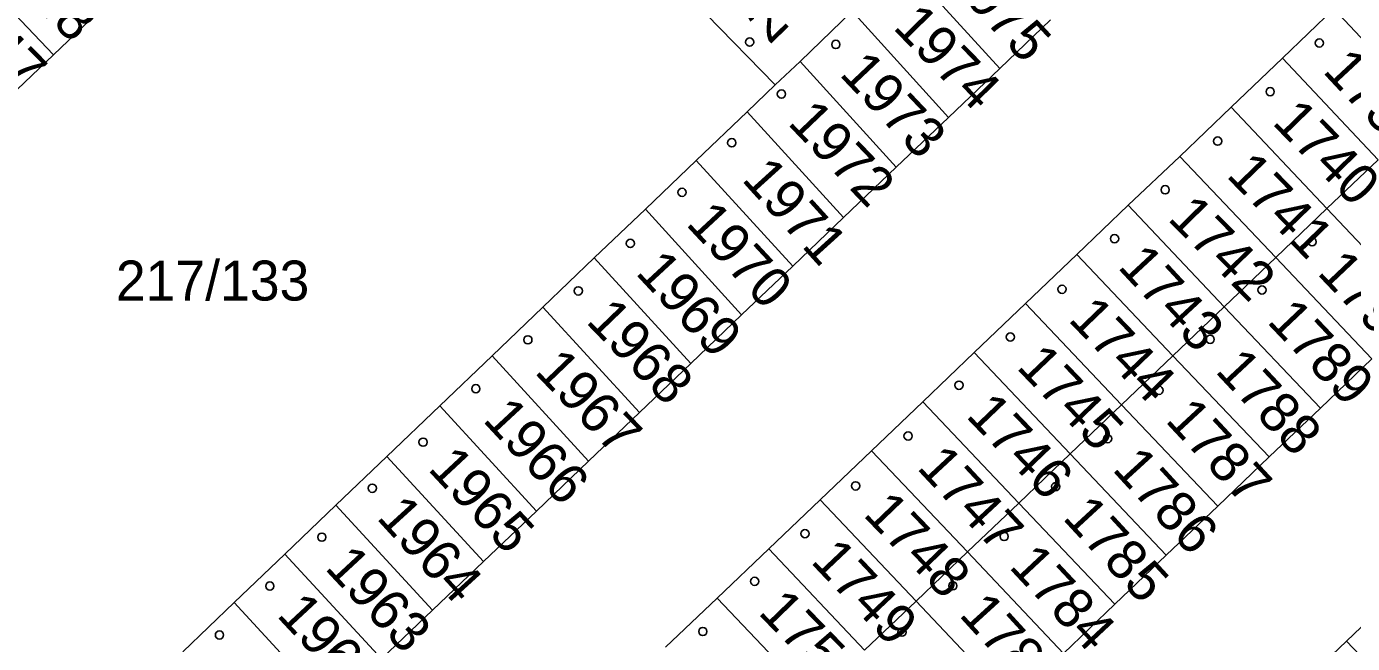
# Model space of a CAD drawing. Extents: x -735249 to -729401, y -1124843 to -1121828.
# Drawn here: x -733413.7 to -733357.4, y -1123214.1 to -1123187.9 of the extents above; entities that cross this region are included whole.
import ezdxf

# ---------------------------------------------------------------- set-up
doc = ezdxf.new("R2010")
doc.units = 0
for name, color, linetype in [('Vrstva 1', 7, 'Continuous'), ('Vrstva 18', 7, 'Continuous'), ('Vrstva 19', 7, 'Continuous'), ('Vrstva 25', 7, 'Continuous')]:
    doc.layers.add(name, color=color, linetype=linetype)

msp = doc.modelspace()

# ---------------------------------------------------------------- linework, layer by layer
at = {"layer": 'Vrstva 1'}
for points in [[(-733416.69, -1123184.71), (-733412.54, -1123189.07)], [(-733376.45, -1123185.14), (-733372.35, -1123189.66)], [(-733410.37, -1123187), (-733412.54, -1123189.07)], [(-733384.81, -1123187.34), (-733381.88, -1123190.35)], [(-733380.83, -1123189.35), (-733378.61, -1123187.22)], [(-733378.61, -1123187.22), (-733374.52, -1123191.73)], [(-733372.35, -1123189.66), (-733370.19, -1123187.59)], [(-733358.16, -1123187.12), (-733360.34, -1123189.21)], [(-733358.16, -1123187.12), (-733354.09, -1123191.44)], [(-733412.54, -1123189.07), (-733414.69, -1123191.13)], [(-733360.34, -1123189.21), (-733362.52, -1123191.3)], [(-733360.34, -1123189.21), (-733356.27, -1123193.53)], [(-733381.88, -1123190.35), (-733380.83, -1123189.35)], [(-733380.83, -1123189.35), (-733376.74, -1123193.85)], [(-733374.52, -1123191.73), (-733372.35, -1123189.66)], [(-733383.07, -1123191.49), (-733381.88, -1123190.35)], [(-733385.24, -1123193.57), (-733383.07, -1123191.49)], [(-733383.07, -1123191.49), (-733378.98, -1123195.99)], [(-733362.52, -1123191.3), (-733364.7, -1123193.39)], [(-733362.52, -1123191.3), (-733358.45, -1123195.61)], [(-733376.74, -1123193.85), (-733374.52, -1123191.73)], [(-733387.4, -1123195.64), (-733385.24, -1123193.57)], [(-733385.24, -1123193.57), (-733381.14, -1123198.06)], [(-733364.7, -1123193.39), (-733366.89, -1123195.47)], [(-733364.7, -1123193.39), (-733360.62, -1123197.69)], [(-733358.45, -1123195.61), (-733356.27, -1123193.53)], [(-733378.98, -1123195.99), (-733376.74, -1123193.85)], [(-733366.89, -1123195.47), (-733369.07, -1123197.56)], [(-733366.89, -1123195.47), (-733362.81, -1123199.78)], [(-733389.57, -1123197.71), (-733387.4, -1123195.64)], [(-733387.4, -1123195.64), (-733383.31, -1123200.13)], [(-733381.14, -1123198.06), (-733378.98, -1123195.99)], [(-733360.62, -1123197.69), (-733358.45, -1123195.61)], [(-733358.45, -1123195.61), (-733354.37, -1123199.92)], [(-733391.75, -1123199.8), (-733389.57, -1123197.71)], [(-733389.57, -1123197.71), (-733385.47, -1123202.2)], [(-733369.07, -1123197.56), (-733371.25, -1123199.65)], [(-733369.07, -1123197.56), (-733364.99, -1123201.87)], [(-733362.81, -1123199.78), (-733360.62, -1123197.69)], [(-733360.62, -1123197.69), (-733356.54, -1123202)], [(-733383.31, -1123200.13), (-733381.14, -1123198.06)], [(-733393.91, -1123201.87), (-733391.75, -1123199.8)], [(-733391.75, -1123199.8), (-733387.65, -1123204.28)], [(-733371.25, -1123199.65), (-733373.43, -1123201.73)], [(-733371.25, -1123199.65), (-733367.17, -1123203.95)], [(-733364.99, -1123201.87), (-733362.81, -1123199.78)], [(-733362.81, -1123199.78), (-733358.73, -1123204.09)], [(-733385.47, -1123202.2), (-733383.31, -1123200.13)], [(-733396.13, -1123204), (-733393.91, -1123201.87)], [(-733393.91, -1123201.87), (-733389.81, -1123206.35)], [(-733387.65, -1123204.28), (-733385.47, -1123202.2)], [(-733373.43, -1123201.73), (-733375.62, -1123203.82)], [(-733373.43, -1123201.73), (-733369.35, -1123206.04)], [(-733367.17, -1123203.95), (-733364.99, -1123201.87)], [(-733364.99, -1123201.87), (-733360.91, -1123206.17)], [(-733358.73, -1123204.09), (-733356.54, -1123202)], [(-733375.62, -1123203.82), (-733377.8, -1123205.91)], [(-733375.62, -1123203.82), (-733371.54, -1123208.13)], [(-733369.35, -1123206.04), (-733367.17, -1123203.95)], [(-733367.17, -1123203.95), (-733363.09, -1123208.26)], [(-733398.38, -1123206.15), (-733396.13, -1123204)], [(-733396.13, -1123204), (-733392.03, -1123208.47)], [(-733389.81, -1123206.35), (-733387.65, -1123204.28)], [(-733360.91, -1123206.17), (-733358.73, -1123204.09)], [(-733400.54, -1123208.22), (-733398.38, -1123206.15)], [(-733398.38, -1123206.15), (-733394.28, -1123210.62)], [(-733377.8, -1123205.91), (-733379.98, -1123208)], [(-733377.8, -1123205.91), (-733373.72, -1123210.21)], [(-733371.54, -1123208.13), (-733369.35, -1123206.04)], [(-733369.35, -1123206.04), (-733365.28, -1123210.35)], [(-733363.09, -1123208.26), (-733360.91, -1123206.17)], [(-733392.03, -1123208.47), (-733389.81, -1123206.35)], [(-733402.71, -1123210.3), (-733400.54, -1123208.22)], [(-733400.54, -1123208.22), (-733396.44, -1123212.69)], [(-733379.98, -1123208), (-733382.16, -1123210.08)], [(-733379.98, -1123208), (-733375.9, -1123212.3)], [(-733373.72, -1123210.21), (-733371.54, -1123208.13)], [(-733371.54, -1123208.13), (-733367.46, -1123212.43)], [(-733365.28, -1123210.35), (-733363.09, -1123208.26)], [(-733394.28, -1123210.62), (-733392.03, -1123208.47)], [(-733382.16, -1123210.08), (-733384.35, -1123212.17)], [(-733382.16, -1123210.08), (-733378.09, -1123214.39)], [(-733404.87, -1123212.36), (-733402.71, -1123210.3)], [(-733402.71, -1123210.3), (-733398.61, -1123214.76)], [(-733396.44, -1123212.69), (-733394.28, -1123210.62)], [(-733375.9, -1123212.3), (-733373.72, -1123210.21)], [(-733373.72, -1123210.21), (-733369.64, -1123214.52)], [(-733367.46, -1123212.43), (-733365.28, -1123210.35)], [(-733407.04, -1123214.45), (-733404.87, -1123212.36)], [(-733404.87, -1123212.36), (-733400.76, -1123216.82)], [(-733384.35, -1123212.17), (-733386.54, -1123214.26)], [(-733384.35, -1123212.17), (-733380.27, -1123216.47)], [(-733378.09, -1123214.39), (-733375.9, -1123212.3)], [(-733375.9, -1123212.3), (-733371.83, -1123216.61)], [(-733357.62, -1123214), (-733355.44, -1123211.92)], [(-733398.61, -1123214.76), (-733396.44, -1123212.69)], [(-733369.64, -1123214.52), (-733367.46, -1123212.43)], [(-733359.8, -1123216.09), (-733357.62, -1123214)], [(-733357.62, -1123214), (-733353.54, -1123218.28)]]:
    msp.add_lwpolyline(points, dxfattribs=at)
at = {"layer": 'Vrstva 25'}
for centre in [(-733382.97, -1123188.53), (-733379.31, -1123188.63), (-733358.77, -1123188.57), (-733381.62, -1123190.74), (-733360.86, -1123190.64), (-733383.73, -1123192.81), (-733363.09, -1123192.74), (-733385.84, -1123194.92), (-733365.32, -1123194.81), (-733388.04, -1123197.09), (-733367.47, -1123196.89), (-733359.08, -1123197.02), (-733369.7, -1123199.04), (-733390.25, -1123199.11), (-733361.21, -1123199.07), (-733392.39, -1123201.19), (-733371.9, -1123201.07), (-733363.41, -1123201.17), (-733394.6, -1123203.27), (-733374.08, -1123203.12), (-733365.58, -1123203.34), (-733396.84, -1123205.54), (-733376.24, -1123205.28), (-733367.76, -1123205.39), (-733399, -1123207.5), (-733378.47, -1123207.4), (-733369.97, -1123207.43), (-733401.14, -1123209.58), (-733380.62, -1123209.43), (-733372.16, -1123209.55), (-733403.35, -1123211.66), (-733382.76, -1123211.46), (-733374.34, -1123211.65), (-733384.96, -1123213.59), (-733376.5, -1123213.62), (-733405.49, -1123213.74)]:
    msp.add_circle(centre, 0.175, dxfattribs=at)

# ---------------------------------------------------------------- texts
at = {"layer": 'Vrstva 18'}
msp.add_text('217/133', height=1.7, dxfattribs=at).set_placement((-733409.89, -1123199.52))
at = {"layer": 'Vrstva 19'}
for s, rotation, p in [('2048', 315.3025, (-733415.318, -1123185.069)), ('2064', 44.0004, (-733382.136, -1123188.668)), ('1975', 312.8025, (-733374.718, -1123185.8)), ('2047', 314.8025, (-733417.468, -1123187.12)), ('1974', 314.4025, (-733376.928, -1123187.932)), ('1973', 313.4025, (-733379.198, -1123189.917)), ('1739', 313.0025, (-733358.668, -1123189.789)), ('1972', 313.7025, (-733381.398, -1123191.996)), ('1740', 314.3025, (-733360.818, -1123191.983)), ('1971', 312.2025, (-733383.348, -1123194.393)), ('1741', 314.1025, (-733362.768, -1123194.224)), ('1970', 312.9025, (-733385.718, -1123196.28)), ('1742', 314.7025, (-733365.258, -1123196.071)), ('1969', 312.8025, (-733387.858, -1123198.36)), ('1743', 312.9025, (-733367.378, -1123198.11)), ('1790', 313.5025, (-733358.908, -1123198.367)), ('1968', 314.0025, (-733389.968, -1123200.434)), ('1744', 313.9025, (-733369.478, -1123200.355)), ('1789', 313.5025, (-733361.038, -1123200.437)), ('1745', 313.7025, (-733371.678, -1123202.376)), ('1967', 313.8025, (-733392.148, -1123202.575)), ('1788', 313.1025, (-733363.238, -1123202.539)), ('1966', 312.9025, (-733394.348, -1123204.62)), ('1746', 313.8025, (-733373.828, -1123204.445)), ('1787', 312.9025, (-733365.358, -1123204.64)), ('1965', 313.0025, (-733396.678, -1123206.699)), ('1747', 313.0025, (-733375.908, -1123206.649)), ('1786', 312.5025, (-733367.608, -1123206.712)), ('1748', 313.9025, (-733378.188, -1123208.645)), ('1964', 312.4025, (-733398.858, -1123208.772)), ('1785', 312.7025, (-733369.718, -1123208.781)), ('1963', 312.9025, (-733401.058, -1123210.91)), ('1749', 313.4025, (-733380.418, -1123210.637)), ('1784', 313.1025, (-733371.998, -1123210.859)), ('1962', 313.0025, (-733403.098, -1123212.919)), ('1750', 314.1025, (-733382.648, -1123212.814)), ('1783', 312.4025, (-733374.118, -1123212.902))]:
    msp.add_text(s, height=1.7, rotation=rotation, dxfattribs=at).set_placement(p)

doc.saveas('drawing.dxf')
